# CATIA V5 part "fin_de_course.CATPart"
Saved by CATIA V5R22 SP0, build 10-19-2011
Part number: fin_de_course
Bounding box of the stored display mesh (mm): x 0 to 10, y -25.3 to 13.9, z -7.95 to 17.25
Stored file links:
  C:\Users\amejo\Downloads\support capteur\fin_de_course.CATPart
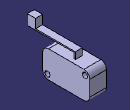
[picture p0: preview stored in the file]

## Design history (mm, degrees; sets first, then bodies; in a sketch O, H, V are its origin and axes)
Body1 (main body)
  Sketch1 on yz-plane, origin (0, 0, 0), H (0, 1, 0), V (0, 0, 1)
    line L1 (-10.5, 7.95) -> (2.3, 7.95)
    line L2 (13.9, 4.55) -> (13.9, -4.55)
    line L3 (10.5, -7.95) -> (-10.5, -7.95)
    line L4 (-13.9, -4.55) -> (-13.9, 4.55)
    point P1 (13.9, -7.95)
    point P2 (3, 7.95)
    line L5 (2.3, 7.95) -> (2.3, 11.25)
    line L6 (3, 11.95) -> (3, 11.95)
    line L7 (3, 11.95) -> (3, 7.95)
    point P4 (3, 11.95)
    point P5 (3, 11.95)
    line L8 (3, 11.95) -> (-20.5, 11.95)
    line L9 (-25.3, 11.25) -> (2.3, 11.25)
    point P6 (-25.3, 11.95)
    point P7 (-25.3, 11.25)
    line L10 (3, 7.95) -> (10.5, 7.95)
    circle A1 centre (11.1, 5.15) radius 1.55
    point P9 (11.1, 5.15)
    circle A2 centre (-11.1, -5.15) radius 1.55
    point P10 (-11.1, -5.15)
    arc A3 centre (10.5, -4.55) radius 3.4 from (13.9, -4.55) to (10.5, -7.95) cw
    point P11 (13.9, -4.55)
    point P12 (10.5, -7.95)
    point P14 (10.5, 7.95)
    point P15 (13.9, 4.55)
    arc A4 centre (10.5, 4.55) radius 3.4 from (13.9, 4.55) to (10.5, 7.95) ccw
    point P16 (-10.5, 7.95)
    point P17 (-13.9, 4.55)
    arc A5 centre (-10.5, 4.55) radius 3.4 from (-13.9, 4.55) to (-10.5, 7.95) cw
    point P19 (-10.5, -7.95)
    point P20 (-13.9, -4.55)
    arc A6 centre (-10.5, -4.55) radius 3.4 from (-13.9, -4.55) to (-10.5, -7.95) ccw
    line L11 (-25.3, 17.25) -> (-20.5, 17.25)
    line L12 (-20.5, 17.25) -> (-20.5, 11.95)
    line L13 (-25.3, 17.25) -> (-25.3, 11.25)
    distance L8 L3 = 19.9
    distance L5 L7 = 0.7
    radius A1 = 1.55
    radius A2 = 1.55
    radius A3 = 3.4
    distance L1 L3 = 15.9
    distance L2 L4 = 27.8
    distance L10 P9 = 2.8
    distance P9 P10 H = 22.2
    distance P10 P9 V = 10.3
    distance P10 L4 = 2.8
    distance P7 P9 H = 36.4
    distance P9 L7 = 8.1
    distance L13 L12 = 4.8
    distance L11 L9 = 6
    distance L8 L9 = 0.7
    horizontal: L1 H, L3 H, L6 H, L8 H, L9 H, L10 H, L11 H
    vertical: L2 V, L4 V, L5 V, L7 V, L12 V, L13 V
    symmetry: L4 L2 V, L1 L3 H, P12 P14 H, P11 P15 H, A3 A4 H, P14 P16 V, P15 P17 V, A4 A5 V, P16 P19 H, P17 P20 H, A5 A6 H
    coincidence: P2 L1, L1 L10, P5 P4, L2 P1, L3 P1
    tangency: A3 L2, A3 L3
  Pad1: profile Sketch1, direction (1, 0, 0), length 10
  Sketch2 on face of Pad1 from Sketch1.L11, origin (0, 0, 17.25), H (1, 0, 0), V (0, 1, 0)
    line L1 (0, 23.5158) -> (3.5, 23.5158)
    line L2 (3.5, 23.5158) -> (3.5, -25.3)
    line L3 (3.5, -25.3) -> (0, -25.3)
    line L4 (0, -25.3) -> (0, 23.5158)
    point P5 (10, 23.5158)
    line L5 (10, 23.5158) -> (7.6, 23.5158)
    line L6 (7.6, 23.5158) -> (7.6, -31.1842)
    line L7 (7.6, -31.1842) -> (10, -31.1842)
    line L8 (10, -31.1842) -> (10, 23.5158)
    distance L4 L2 = 3.5
    distance L6 L8 = 2.4
    horizontal: L1 H, L3 H, L5 H, L7 H
    vertical: L2 V, L4 V, L6 V, L8 V
    coincidence: P5 L1
  Pocket1: profile Sketch2, direction (0, 0, -1), length 9.3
